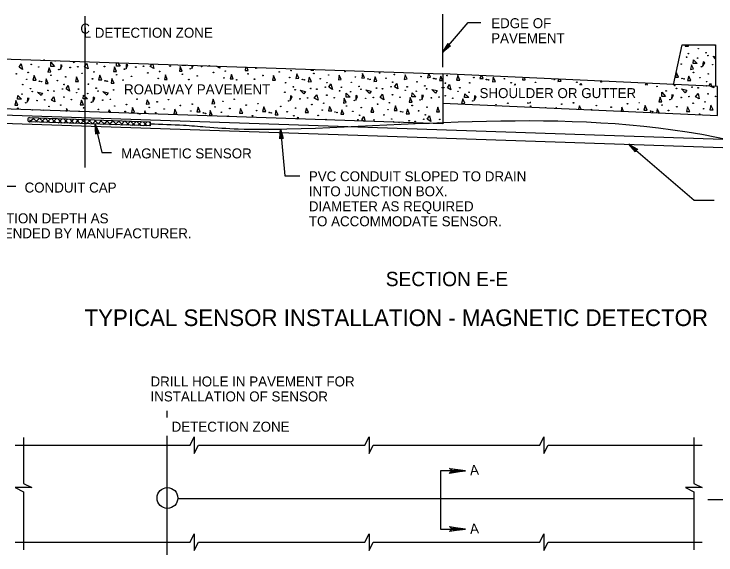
# Model space of a CAD drawing. Extents: x 2709 to 3899, y 22 to 1210.
# Drawn here: x 2819.9 to 3030.6, y 167.3 to 329.8 of the extents above; entities that cross this region are included whole.
import ezdxf

# ---------------------------------------------------------------- set-up
doc = ezdxf.new("R2010")
doc.units = 0
doc.layers.add('2', color=7, linetype='Continuous')
doc.layers.add('3', color=7, linetype='Continuous')

# ---------------------------------------------------------------- blocks, each defined once
blk = doc.blocks.new('RARROW')
at = {"layer": '3'}
blk.add_lwpolyline([(-2.2695, 0.285), (-2.184875, 0.12075), (0, 0), (-2.2695, 0.285), (-2.38575, 0.384625), (0, 0), (-2.183125, -0.108), (-2.262875, -0.2705), (0, 0), (-2.38575, -0.379125), (-2.262875, -0.2705)], dxfattribs=at)

msp = doc.modelspace()

# ---------------------------------------------------------------- linework, layer by layer
at = {"layer": '2'}
for p, q in [((2841.15, 329.17), (2841.15, 283.67)), ((2948.65, 313.79), (2948.65, 329.79)), ((2948.65, 318.29), (2956.28, 327.29)), ((2956.28, 327.29), (2960.03, 327.29)), ((2816.4, 299.54), (3040.28, 291.92)), ((2816.4, 297.04), (3040.28, 289.42)), ((2844.26, 296.74), (2846.28, 288.17)), ((2899.93, 295.3), (2901.15, 281.17)), ((3004.53, 290.67), (3024.15, 273.92)), ((2846.28, 288.17), (2849.15, 288.17)), ((2901.15, 281.17), (2905.65, 281.17)), ((2817.15, 278.04), (2820.4, 278.04)), ((3024.15, 273.92), (3030.15, 273.92)), ((2865.85, 208.54), (2865.85, 210.54)), ((2865.85, 167.29), (2865.85, 203.04)), ((2868.97, 184.29), (3023.97, 184.29))]:
    msp.add_line(p, q, dxfattribs=at)
for points in [[(3017.9, 308.54), (3020.53, 320.54), (3030.53, 320.54), (3030.53, 308.04), (3030.53, 308.04)], [(3021.53, 320.54), (3021.4, 320.17)], [(3022.4, 320.17), (3022.28, 320.54)], [(3021.4, 320.17), (3022.4, 320.17)], [(2801.15, 316.79), (2948.65, 311.79), (2948.65, 296.79), (2801.15, 301.79), (2801.15, 301.79)], [(3030.53, 316.29), (3029.78, 317.17)], [(3029.78, 317.17), (3030.53, 316.92)], [(2837.9, 315.17), (2837.65, 315.54)], [(2838.15, 315.54), (2837.9, 315.17)], [(2850.65, 314.17), (2850.65, 315.04)], [(2851.78, 314.17), (2850.65, 314.17)], [(2851.03, 315.04), (2851.78, 314.17)], [(2860.78, 314.04), (2861.28, 314.67)], [(2861.53, 314.67), (2861.9, 313.42)], [(2870.28, 314.29), (2870.28, 314.42)], [(2871.53, 314.29), (2870.28, 314.29)], [(2871.53, 314.42), (2871.53, 314.29)], [(2873.28, 314.29), (2873.28, 313.42)], [(2873.28, 313.42), (2873.65, 314.29)], [(2861.9, 313.42), (2860.78, 314.04)], [(2881.65, 313.54), (2880.78, 314.04)], [(2881.53, 314.04), (2881.65, 313.54)], [(2889.4, 313.79), (2889.28, 312.79)], [(2889.28, 312.79), (2890.15, 312.79)], [(2890.15, 312.79), (2889.78, 313.79)], [(2892.9, 313.67), (2892.9, 313.54)], [(2892.9, 313.54), (2893.03, 313.67)], [(2909.03, 313.04), (2909.03, 312.92)], [(2909.03, 312.92), (2909.9, 312.92)], [(2909.9, 312.92), (2909.78, 313.04)], [(3018.78, 312.17), (3018.53, 310.79)], [(3019.4, 310.79), (3018.78, 312.17)], [(2944.28, 311.92), (2944.03, 310.67)], [(2944.03, 310.67), (2944.9, 310.79)], [(2944.9, 310.79), (2944.4, 311.92)], [(2948.03, 311.17), (2947.65, 309.79)], [(2948.53, 309.79), (2948.03, 311.17)], [(2960.03, 311.17), (2959.78, 310.42)], [(2959.78, 310.42), (2960.78, 310.42)], [(2960.78, 310.42), (2960.4, 311.17)], [(2972.65, 310.67), (2972.53, 310.04)], [(2972.53, 310.04), (2973.4, 310.04)], [(2973.4, 310.04), (2973.28, 310.67)], [(2983.4, 310.17), (2983.15, 309.54)], [(2984.15, 309.67), (2983.9, 310.17)], [(3018.53, 310.79), (3019.4, 310.79)], [(2947.65, 309.79), (2948.53, 309.79)], [(2970.15, 308.42), (2970.4, 308.79), (2970.4, 308.42)], [(2983.15, 309.54), (2984.15, 309.67)], [(2989.78, 308.42), (2990.15, 308.92), (2990.28, 308.42)], [(3009.53, 308.42), (3009.78, 308.92)], [(3009.9, 308.92), (3010.03, 308.42)], [(3028.53, 308.17), (3029.03, 309.04)], [(3029.03, 309.04), (3029.28, 308.17)], [(3030.03, 307.67), (3029.15, 308.04)], [(3029.9, 308.04), (3030.03, 307.67)], [(2954.65, 304.29), (2954.28, 302.92)], [(2955.28, 303.04), (2954.65, 304.29)], [(2958.65, 304.92), (2958.15, 305.17), (2958.03, 303.79), (2958.65, 304.92)], [(2835.65, 301.42), (2835.53, 300.54)], [(2836.15, 300.54), (2835.65, 301.42)], [(2855.4, 301.67), (2855.15, 300.17)], [(2856.03, 300.29), (2855.4, 301.67)], [(2954.28, 302.92), (2955.28, 303.04)], [(2974.03, 303.17), (2974.03, 303.04), (2975.03, 303.17), (2974.9, 303.17)], [(2982.65, 301.67), (2982.65, 301.42)], [(2982.78, 301.42), (2982.65, 301.67)], [(2989.65, 302.17), (2989.4, 301.17)], [(2990.15, 301.17), (2989.65, 302.17)], [(3002.4, 301.79), (3002.15, 300.54)], [(3002.9, 300.54), (3002.4, 301.79)], [(2828.65, 300.92), (2828.65, 300.79)], [(2828.78, 300.79), (2828.65, 300.92)], [(2839.4, 300.54), (2839.4, 300.42)], [(2839.4, 300.42), (2839.4, 300.54)], [(2848.4, 301.04), (2848.15, 300.17)], [(2848.9, 300.17), (2848.4, 301.04)], [(2855.15, 300.17), (2856.03, 300.29)], [(2859.15, 300.67), (2858.9, 299.79)], [(2859.53, 299.79), (2859.15, 300.67)], [(2868.15, 301.17), (2867.9, 299.79)], [(2867.9, 299.79), (2868.78, 299.92)], [(2868.78, 299.92), (2868.15, 301.17)], [(2878.78, 300.79), (2878.53, 299.42)], [(2878.53, 299.42), (2879.4, 299.42)], [(2879.4, 299.42), (2878.78, 300.79)], [(2993.28, 301.17), (2993.28, 300.92)], [(2993.4, 300.92), (2993.28, 301.17)], [(3013.03, 301.29), (3012.78, 300.04)], [(3013.65, 300.04), (3013.03, 301.29)], [(2824.53, 298.67), (2860.78, 297.42), (2860.78, 296.17), (2824.53, 297.42), (2824.53, 297.42)], [(2824.53, 297.42), (2825.78, 298.54)], [(2825.15, 297.42), (2824.53, 298.04)], [(2826.9, 297.29), (2825.65, 298.54)], [(2826.28, 297.29), (2827.53, 298.54)], [(2828.78, 297.29), (2827.53, 298.54)], [(2828.03, 297.29), (2829.15, 298.42)], [(2830.65, 297.17), (2829.28, 298.42)], [(2829.65, 297.17), (2830.9, 298.42)], [(2832.4, 297.17), (2831.15, 298.42)], [(2831.4, 297.17), (2832.65, 298.42)], [(2834.28, 297.04), (2833.03, 298.29)], [(2833.15, 297.04), (2834.28, 298.29)], [(2834.78, 297.04), (2836.03, 298.29)], [(2836.15, 297.04), (2834.78, 298.29)], [(2836.53, 296.92), (2837.78, 298.17)], [(2837.9, 296.92), (2836.65, 298.17)], [(2838.28, 296.92), (2839.4, 298.17)], [(2839.78, 296.92), (2838.53, 298.17)], [(2839.9, 296.92), (2841.15, 298.04)], [(2841.65, 296.79), (2840.28, 298.04)], [(2841.65, 296.79), (2842.9, 298.04)], [(2843.4, 296.79), (2842.15, 298.04)], [(2843.4, 296.79), (2844.53, 297.92)], [(2845.28, 296.67), (2844.03, 297.92)], [(2845.03, 296.67), (2846.28, 297.92)], [(2847.03, 296.67), (2845.78, 297.92)], [(2846.78, 296.67), (2848.03, 297.79)], [(2848.9, 296.54), (2847.65, 297.79)], [(2848.53, 296.54), (2849.65, 297.79)], [(2850.78, 296.54), (2849.4, 297.79)], [(2850.15, 296.54), (2851.4, 297.67)], [(2852.53, 296.42), (2851.28, 297.67)], [(2851.9, 296.42), (2853.15, 297.67)], [(2854.4, 296.42), (2853.15, 297.67)], [(2853.65, 296.42), (2854.78, 297.54)], [(2856.28, 296.29), (2854.9, 297.54)], [(2855.28, 296.29), (2856.53, 297.54)], [(2858.03, 296.29), (2856.78, 297.54)], [(2857.03, 296.29), (2858.28, 297.54)], [(2859.9, 296.17), (2858.65, 297.42)], [(2858.78, 296.17), (2859.9, 297.42)], [(2860.78, 297.04), (2860.4, 297.42)], [(2904.78, 298.17), (2905.15, 298.79)], [(2905.15, 298.79), (2905.28, 298.17)], [(2924.28, 298.04), (2924.9, 299.04)], [(2925.03, 297.54), (2924.28, 298.04)], [(2924.9, 299.04), (2925.28, 297.54)], [(2935.4, 297.17), (2935.28, 297.29)], [(2935.28, 297.29), (2935.65, 297.17)], [(2860.53, 296.17), (2860.78, 296.54)], [(2820.22, 200.29), (2872.72, 200.29), (2873.97, 202.79), (2873.97, 197.79), (2875.22, 200.29), (2925.22, 200.29), (2926.47, 202.79), (2926.47, 197.79), (2927.72, 200.29), (2977.72, 200.29), (2978.97, 202.79), (2978.97, 197.79), (2980.22, 200.29), (3026.47, 200.29)], [(2822.72, 202.54), (2822.72, 188.79), (2825.22, 187.54), (2820.22, 187.54), (2822.72, 186.29), (2822.72, 168.79)], [(3023.97, 202.54), (3023.97, 188.79), (3026.47, 187.54), (3021.47, 187.54), (3023.97, 186.29), (3023.97, 168.79)], [(2955.47, 192.54), (2947.97, 192.54), (2947.97, 180.04), (2947.97, 175.04), (2955.47, 175.04)], [(2950.85, 193.16), (2951.1, 192.79), (2955.47, 192.54), (2950.85, 193.16), (2950.6, 193.29), (2955.47, 192.54), (2951.1, 192.29), (2950.85, 192.04), (2955.47, 192.54), (2950.6, 191.79), (2950.85, 192.04)], [(3028.22, 183.91), (3035.72, 183.91), (3035.72, 191.41)], [(2950.85, 175.66), (2951.1, 175.29), (2955.47, 175.04), (2950.85, 175.66), (2950.6, 175.79), (2955.47, 175.04), (2951.1, 174.79), (2950.85, 174.54), (2955.47, 175.04), (2950.6, 174.29), (2950.85, 174.54)], [(2820.22, 171.16), (2872.72, 171.16), (2873.97, 173.66), (2873.97, 168.66), (2875.22, 171.16), (2925.22, 171.16), (2926.47, 173.66), (2926.47, 168.66), (2927.72, 171.16), (2977.72, 171.16), (2978.97, 173.66), (2978.97, 168.66), (2980.22, 171.16), (3026.47, 171.16)]]:
    msp.add_lwpolyline(points, dxfattribs=at)
for points in [[(2821.4, 313.79), (2822.03, 314.79), (2822.4, 313.17)], [(2830.9, 314.04), (2830.9, 315.29), (2832.03, 314.04)], [(2834.28, 314.29), (2833.9, 314.54), (2833.78, 313.17)], [(2841.03, 313.92), (2841.78, 314.92), (2842.15, 313.29)], [(2854.03, 314.54), (2853.53, 314.67), (2853.53, 313.29)], [(3023.28, 314.54), (3023.03, 313.17), (3023.9, 313.29)], [(3023.78, 314.92), (3023.9, 316.04), (3025.03, 314.92)], [(3027.28, 315.17), (3026.78, 315.42), (3026.65, 314.04)], [(2830.4, 313.67), (2830.03, 312.29), (2830.9, 312.42)], [(2850.03, 313.92), (2849.78, 312.54), (2850.65, 312.54)], [(2869.78, 314.04), (2869.53, 312.67), (2870.4, 312.67)], [(2825.9, 311.29), (2825.53, 309.92), (2826.53, 309.92)], [(2829.53, 310.29), (2829.28, 308.92), (2830.15, 308.92)], [(2838.65, 310.92), (2838.28, 309.54), (2839.28, 309.54)], [(2845.65, 311.42), (2845.28, 310.04), (2846.28, 310.04)], [(2849.28, 310.42), (2849.03, 309.04), (2849.9, 309.04)], [(2865.4, 311.54), (2865.03, 310.17), (2865.9, 310.17)], [(2885.15, 311.67), (2884.78, 310.29), (2885.65, 310.29)], [(2897.78, 311.29), (2897.53, 309.92), (2898.4, 309.92)], [(2904.78, 311.79), (2904.53, 310.42), (2905.4, 310.54)], [(2908.53, 310.79), (2908.15, 309.42), (2909.15, 309.54)], [(2917.53, 311.42), (2917.28, 310.04), (2918.15, 310.17)], [(2924.53, 311.92), (2924.28, 310.54), (2925.15, 310.67)], [(2928.28, 310.92), (2927.9, 309.54), (2928.78, 309.67)], [(2937.28, 311.54), (2937.03, 310.17), (2937.9, 310.29)], [(3031.15, 308.04), (2948.65, 311.79), (2948.65, 303.04), (3031.15, 299.29)], [(2953.15, 311.29), (2952.78, 309.92), (2953.78, 309.92)], [(2963.78, 310.79), (2963.53, 309.42), (2964.4, 309.54)], [(3022.53, 311.17), (3022.15, 309.79), (3023.15, 309.79)], [(2835.53, 307.29), (2836.15, 308.29), (2836.53, 306.67)], [(2914.4, 307.79), (2915.03, 308.79), (2915.53, 307.17)], [(2934.15, 307.92), (2934.78, 308.92), (2935.15, 307.29)], [(2950.03, 307.67), (2950.65, 308.67), (2951.03, 307.04)], [(2828.4, 306.04), (2828.03, 305.29), (2826.9, 306.29)], [(2848.15, 306.17), (2847.78, 305.42), (2846.53, 306.54)], [(2907.4, 306.54), (2906.9, 305.79), (2905.78, 306.92)], [(2919.65, 304.79), (2919.65, 306.04), (2920.78, 304.79)], [(2927.15, 306.67), (2926.65, 305.92), (2925.53, 307.04)], [(2929.78, 304.67), (2930.53, 305.67), (2930.9, 304.04)], [(2939.28, 304.92), (2939.4, 306.17), (2940.53, 304.92)], [(2946.9, 306.79), (2946.4, 306.04), (2945.28, 307.17)], [(2955.15, 304.67), (2955.28, 305.79), (2956.4, 304.67)], [(3014.4, 305.04), (3014.4, 306.29), (3015.53, 305.04)], [(3021.9, 306.92), (3021.4, 306.17), (3020.28, 307.29)], [(3024.53, 304.92), (3025.28, 305.92), (3025.65, 304.29)], [(2820.4, 303.79), (2820.15, 302.42), (2821.03, 302.42)], [(2820.9, 304.17), (2821.03, 305.29), (2822.15, 304.17)], [(2824.4, 304.42), (2823.9, 304.54), (2823.78, 303.29)], [(2831.15, 303.92), (2831.78, 304.92), (2832.15, 303.42)], [(2840.15, 303.92), (2839.78, 302.54), (2840.78, 302.54)], [(2840.65, 304.29), (2840.78, 305.42), (2841.9, 304.29)], [(2844.15, 304.54), (2843.65, 304.79), (2843.53, 303.42)], [(2859.9, 304.04), (2859.53, 302.67), (2860.53, 302.79)], [(2879.65, 304.17), (2879.28, 302.79), (2880.15, 302.92)], [(2903.4, 304.92), (2902.9, 305.17), (2902.78, 303.79)], [(2910.03, 304.54), (2910.78, 305.54), (2911.15, 303.92)], [(2919.03, 304.54), (2918.78, 303.04), (2919.65, 303.17)], [(2923.03, 305.04), (2922.53, 305.29), (2922.53, 303.92)], [(2938.78, 304.67), (2938.53, 303.29), (2939.4, 303.29)], [(2942.78, 305.29), (2942.28, 305.42), (2942.28, 304.04)], [(3013.9, 304.79), (3013.53, 303.42), (3014.4, 303.42)], [(3017.9, 305.42), (3017.4, 305.54), (3017.28, 304.17)], [(2875.15, 301.79), (2874.78, 300.42), (2875.78, 300.42)], [(2887.9, 301.42), (2887.53, 300.04), (2888.53, 300.04)], [(2894.9, 301.92), (2894.53, 300.54), (2895.53, 300.54)], [(2907.65, 301.54), (2907.28, 300.17), (2908.28, 300.17)], [(2914.65, 302.04), (2914.28, 300.67), (2915.28, 300.67)], [(2927.4, 301.67), (2927.03, 300.29), (2927.9, 300.29)], [(2934.4, 302.17), (2934.03, 300.79), (2934.9, 300.79)], [(2947.15, 301.79), (2946.78, 300.42), (2947.65, 300.42)], [(3009.4, 302.29), (3009.03, 300.92), (3010.03, 300.92)], [(3022.15, 301.92), (3021.78, 300.54), (3022.78, 300.54)], [(3029.15, 302.42), (3028.78, 301.04), (3029.78, 301.04)], [(2898.53, 300.92), (2898.28, 299.54), (2899.15, 299.54)], [(2918.28, 301.04), (2918.03, 299.67), (2918.9, 299.67)], [(2938.03, 301.17), (2937.65, 299.79), (2938.65, 299.79)], [(2943.9, 298.17), (2944.65, 299.17), (2945.03, 297.54)]]:
    msp.add_lwpolyline(points, close=True, dxfattribs=at)
for centre, radius in [((3030.39, 320.4), 0.0919), ((3025.35, 319.39), 0.0919), ((3021.82, 316.83), 0.0919), ((3022.38, 317.9), 0.0919), ((3025.14, 316.55), 0.0919), ((3027.69, 318.17), 0.0919), ((3028.24, 317.3), 0.0919), ((2825.05, 314.66), 0.0919), ((2828.88, 315.97), 0.0919), ((2832.2, 315.69), 0.0919), ((2839.02, 313.97), 0.0919), ((2844.78, 314.8), 0.0919), ((2847.03, 314.02), 0.0919), ((2858.76, 314.11), 0.0919), ((2866.77, 314.16), 0.0919), ((2876.19, 313.99), 0.0919), ((2878.49, 314.25), 0.0919), ((3020.24, 314.75), 0.0919), ((3029.66, 314.58), 0.0919), ((2824.11, 312.25), 0.0919), ((2827.3, 313.88), 0.0919), ((2833.32, 313.09), 0.0919), ((2836.72, 313.72), 0.0919), ((2840.3, 311.97), 0.0919), ((2843.85, 312.39), 0.0919), ((2853.05, 313.23), 0.0919), ((2856.46, 313.86), 0.0919), ((2860.04, 312.11), 0.0919), ((2863.58, 312.52), 0.0919), ((2872.79, 313.36), 0.0919), ((2879.77, 312.25), 0.0919), ((2883.32, 312.66), 0.0919), ((2892.52, 313.5), 0.0919), ((2899.51, 312.39), 0.0919), ((2903.05, 312.8), 0.0919), ((2909.9, 311.96), 0.0919), ((2919.24, 312.52), 0.0919), ((2929.63, 312.1), 0.0919), ((3023.9, 312.27), 0.0919), ((3026.26, 313.95), 0.0919), ((2820.57, 311.83), 0.0919), ((2823.7, 310.18), 0.0919), ((2830.96, 311.41), 0.0919), ((2832.89, 309.81), 0.0919), ((2835.41, 310.93), 0.0919), ((2843.43, 310.32), 0.0919), ((2850.69, 311.55), 0.0919), ((2852.62, 309.95), 0.0919), ((2855.14, 311.07), 0.0919), ((2863.17, 310.45), 0.0919), ((2870.43, 311.69), 0.0919), ((2872.36, 310.09), 0.0919), ((2874.88, 311.2), 0.0919), ((2882.9, 310.59), 0.0919), ((2886.72, 310.02), 0.0919), ((2890.16, 311.83), 0.0919), ((2892.09, 310.22), 0.0919), ((2894.61, 311.34), 0.0919), ((2902.64, 310.73), 0.0919), ((2906.45, 310.15), 0.0919), ((2907.05, 310.02), 0.0919), ((2911.82, 310.36), 0.0919), ((2914.35, 311.48), 0.0919), ((2922.37, 310.87), 0.0919), ((2926.19, 310.29), 0.0919), ((2926.79, 310.16), 0.0919), ((2931.56, 310.5), 0.0919), ((2934.08, 311.62), 0.0919), ((2942.11, 311.01), 0.0919), ((2945.92, 310.43), 0.0919), ((2946.52, 310.3), 0.0919), ((2949.91, 311.33), 0.0919), ((2957.94, 310.71), 0.0919), ((2961.75, 310.14), 0.0919), ((2962.35, 310), 0.0919), ((2967.12, 310.35), 0.0919), ((2981.49, 310.28), 0.0919), ((2982.09, 310.14), 0.0919), ((3020.45, 310.46), 0.0919), ((3021.06, 310.33), 0.0919), ((3025.83, 310.67), 0.0919), ((3028.35, 311.79), 0.0919), ((2822.48, 308.59), 0.0919), ((2827.52, 309.6), 0.0919), ((2828.12, 309.47), 0.0919), ((2834.9, 308.62), 0.0919), ((2842.21, 308.73), 0.0919), ((2847.25, 309.74), 0.0919), ((2847.85, 309.61), 0.0919), ((2901.41, 309.15), 0.0919), ((2903.75, 307.92), 0.0919), ((2913.35, 307.83), 0.0919), ((2913.84, 309.17), 0.0919), ((2918.18, 307.79), 0.0919), ((2921.15, 309.28), 0.0919), ((2923.49, 308.06), 0.0919), ((2933.09, 307.96), 0.0919), ((2933.57, 309.31), 0.0919), ((2937.91, 307.93), 0.0919), ((2940.88, 309.42), 0.0919), ((2943.22, 308.2), 0.0919), ((2948.45, 307.69), 0.0919), ((2948.92, 307.67), 0.0919), ((2949.41, 309.02), 0.0919), ((2956.71, 309.13), 0.0919), ((2969.14, 309.16), 0.0919), ((2976.45, 309.27), 0.0919), ((2988.87, 309.3), 0.0919), ((2996.18, 309.41), 0.0919), ((3012.95, 308.05), 0.0919), ((3018.26, 308.32), 0.0919), ((3023.48, 307.81), 0.0919), ((3027.84, 309.48), 0.0919), ((3027.86, 308.22), 0.0919), ((2822.26, 305.75), 0.0919), ((2824.82, 307.37), 0.0919), ((2825.36, 306.5), 0.0919), ((2830.04, 306.86), 0.0919), ((2831.86, 306.66), 0.0919), ((2834.42, 307.27), 0.0919), ((2838.68, 306.17), 0.0919), ((2839.24, 307.24), 0.0919), ((2841.99, 305.89), 0.0919), ((2844.55, 307.51), 0.0919), ((2845.1, 306.64), 0.0919), ((2849.78, 307), 0.0919), ((2901.2, 306.3), 0.0919), ((2904.3, 307.05), 0.0919), ((2908.98, 307.41), 0.0919), ((2910.8, 307.21), 0.0919), ((2917.62, 306.73), 0.0919), ((2920.93, 306.44), 0.0919), ((2924.04, 307.19), 0.0919), ((2928.72, 307.55), 0.0919), ((2930.53, 307.35), 0.0919), ((2933.52, 305.55), 0.0919), ((2937.35, 306.87), 0.0919), ((2940.67, 306.58), 0.0919), ((2943.77, 307.33), 0.0919), ((2953.18, 306.57), 0.0919), ((2953.74, 307.64), 0.0919), ((2956.5, 306.29), 0.0919), ((3015.7, 306.7), 0.0919), ((3018.81, 307.45), 0.0919), ((3025.3, 307.61), 0.0919), ((3028.29, 305.81), 0.0919), ((2826.78, 303.78), 0.0919), ((2829.09, 304.03), 0.0919), ((2834.85, 304.86), 0.0919), ((2837.1, 304.09), 0.0919), ((2846.52, 303.92), 0.0919), ((2848.82, 304.17), 0.0919), ((2856.83, 304.22), 0.0919), ((2862.85, 303.43), 0.0919), ((2866.25, 304.06), 0.0919), ((2882.59, 303.57), 0.0919), ((2885.99, 304.2), 0.0919), ((2902.32, 303.7), 0.0919), ((2905.72, 304.33), 0.0919), ((2908.03, 304.59), 0.0919), ((2913.79, 305.41), 0.0919), ((2916.04, 304.64), 0.0919), ((2922.06, 303.84), 0.0919), ((2925.46, 304.47), 0.0919), ((2927.76, 304.72), 0.0919), ((2935.77, 304.78), 0.0919), ((2941.79, 303.98), 0.0919), ((2945.19, 304.61), 0.0919), ((2947.5, 304.86), 0.0919), ((2949.35, 305.26), 0.0919), ((2951.6, 304.48), 0.0919), ((2957.62, 303.69), 0.0919), ((3016.83, 304.1), 0.0919), ((3020.23, 304.73), 0.0919), ((3022.53, 304.98), 0.0919), ((3030.54, 305.04), 0.0919), ((2821.02, 301.48), 0.0919), ((2823.38, 303.15), 0.0919), ((2830.37, 302.03), 0.0919), ((2833.91, 302.45), 0.0919), ((2840.76, 301.61), 0.0919), ((2843.12, 303.29), 0.0919), ((2850.1, 302.17), 0.0919), ((2853.65, 302.59), 0.0919), ((2860.49, 301.75), 0.0919), ((2869.84, 302.31), 0.0919), ((2873.38, 302.73), 0.0919), ((2880.23, 301.89), 0.0919), ((2884.67, 301.41), 0.0919), ((2889.57, 302.45), 0.0919), ((2893.12, 302.86), 0.0919), ((2899.96, 302.03), 0.0919), ((2904.41, 301.54), 0.0919), ((2909.3, 302.59), 0.0919), ((2912.85, 303), 0.0919), ((2919.7, 302.17), 0.0919), ((2924.14, 301.68), 0.0919), ((2929.04, 302.73), 0.0919), ((2932.58, 303.14), 0.0919), ((2939.43, 302.3), 0.0919), ((2943.88, 301.82), 0.0919), ((2948.77, 302.86), 0.0919), ((2964.6, 302.57), 0.0919), ((2968.15, 302.98), 0.0919), ((2975, 302.15), 0.0919), ((2979.44, 301.67), 0.0919), ((2984.34, 302.71), 0.0919), ((2987.88, 303.12), 0.0919), ((2994.73, 302.29), 0.0919), ((2999.18, 301.8), 0.0919), ((3004.07, 302.85), 0.0919), ((3014.47, 302.43), 0.0919), ((3018.91, 301.94), 0.0919), ((3023.81, 302.99), 0.0919), ((3026.94, 301.33), 0.0919), ((3027.35, 303.4), 0.0919), ((2825.47, 300.99), 0.0919), ((2845.21, 301.13), 0.0919), ((2853.23, 300.52), 0.0919), ((2857.05, 299.94), 0.0919), ((2857.65, 299.81), 0.0919), ((2862.42, 300.15), 0.0919), ((2864.94, 301.27), 0.0919), ((2872.97, 300.66), 0.0919), ((2876.78, 300.08), 0.0919), ((2877.38, 299.95), 0.0919), ((2882.15, 300.29), 0.0919), ((2891.48, 299.21), 0.0919), ((2892.7, 300.79), 0.0919), ((2896.52, 300.22), 0.0919), ((2897.12, 300.08), 0.0919), ((2901.89, 300.43), 0.0919), ((2903.9, 299.24), 0.0919), ((2911.21, 299.35), 0.0919), ((2912.44, 300.93), 0.0919), ((2916.25, 300.36), 0.0919), ((2916.85, 300.22), 0.0919), ((2921.62, 300.56), 0.0919), ((2923.64, 299.38), 0.0919), ((2930.95, 299.49), 0.0919), ((2932.17, 301.07), 0.0919), ((2935.99, 300.49), 0.0919), ((2936.59, 300.36), 0.0919), ((2941.36, 300.7), 0.0919), ((2943.37, 299.51), 0.0919), ((3007.21, 301.19), 0.0919), ((3011.02, 300.62), 0.0919), ((3011.62, 300.48), 0.0919), ((3016.39, 300.82), 0.0919), ((3025.72, 299.75), 0.0919), ((2884.17, 299.1), 0.0919), ((2913.55, 298.12), 0.0919), ((2923.15, 298.03), 0.0919), ((2927.98, 297.99), 0.0919), ((2933.29, 298.26), 0.0919), ((2933.83, 297.39), 0.0919), ((2938.51, 297.75), 0.0919), ((2940.33, 297.55), 0.0919), ((2942.89, 298.17), 0.0919), ((2947.71, 298.13), 0.0919), ((2947.15, 297.07), 0.0919), ((2865.93, 184.4), 3.12)]:
    msp.add_circle(centre, radius, dxfattribs=at)
for centre, radius, start, end in [((3007.62, 303.26), 0.0919, 187.6668, 352.354), ((2824.62, 298.06), 0.633, 100.3114, 261.7056)]:
    msp.add_arc(centre, radius, start, end, dxfattribs=at)
msp.add_spline([(2860.78, 296.79), (2870.78, 296.42), (2877.4, 295.92), (2887.15, 295.29), (2901.78, 295.29), (3039.53, 290.92), (3042.28, 290.54), (3046.03, 291.17), (3050.15, 290.92), (3050.15, 291.42), (3050.4, 293.79), (3051.65, 296.17), (3053.4, 297.67), (3055.65, 298.79), (3057.78, 299.42)], degree=3, dxfattribs=at)

# ---------------------------------------------------------------- block references
for p, xscale, yscale, rotation in [((2948.65, 318.29), 1.2574347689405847, 1.3092961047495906, -130.33386613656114), ((2844.26, 296.74), 1.257434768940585, 1.3092961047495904, 103.6052684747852), ((2899.93, 295.3), 1.2574347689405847, 1.3092961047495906, 94.8622730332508), ((3004.53, 290.67), 1.2574347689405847, 1.3092961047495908, 139.88445274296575)]:
    msp.add_blockref('RARROW', p, dxfattribs=dict(at, xscale=xscale, yscale=yscale, rotation=rotation))

# ---------------------------------------------------------------- texts
for s, height, p in [('C', 3, (2839.78, 323.92)), ('EDGE OF', 3, (2963.15, 325.54)), ('L DETECTION ZONE', 3, (2840.78, 322.67)), ('PAVEMENT', 3, (2963.15, 321.04)), ('ROADWAY PAVEMENT', 3, (2852.9, 305.67)), ('SHOULDER OR GUTTER', 3, (2959.65, 304.54)), ('MAGNETIC SENSOR', 3, (2852.03, 286.42)), ('PVC CONDUIT SLOPED TO DRAIN', 3, (2908.4, 279.54)), ('CONDUIT CAP', 3, (2823.03, 276.17)), ('INTO JUNCTION BOX.', 3, (2908.4, 275.04)), ('DIAMETER AS REQUIRED', 3, (2908.4, 270.54)), ('INSTALLATION DEPTH AS', 3, (2798.53, 266.92)), ('TO ACCOMMODATE SENSOR.', 3, (2908.4, 266.04)), ('RECOMMENDED BY MANUFACTURER.', 3, (2798.53, 262.42)), ('SECTION E-E', 4.3, (2931.5, 248.04)), ('TYPICAL SENSOR INSTALLATION - MAGNETIC DETECTOR', 5, (2841.03, 236.06)), ('DRILL HOLE IN PAVEMENT FOR', 3, (2860.85, 217.91)), ('INSTALLATION OF SENSOR', 3, (2860.85, 213.41)), ('  DETECTION ZONE', 3, (2864.96, 204.32))]:
    msp.add_text(s, height=height, dxfattribs=at).set_placement(p)
for p in [(2956.87, 191.22), (2956.88, 173.59)]:
    msp.add_text('A', height=3, rotation=5, dxfattribs=at).set_placement(p)

doc.saveas('drawing.dxf')
